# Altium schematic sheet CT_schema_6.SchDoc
size 226 x 144 mm
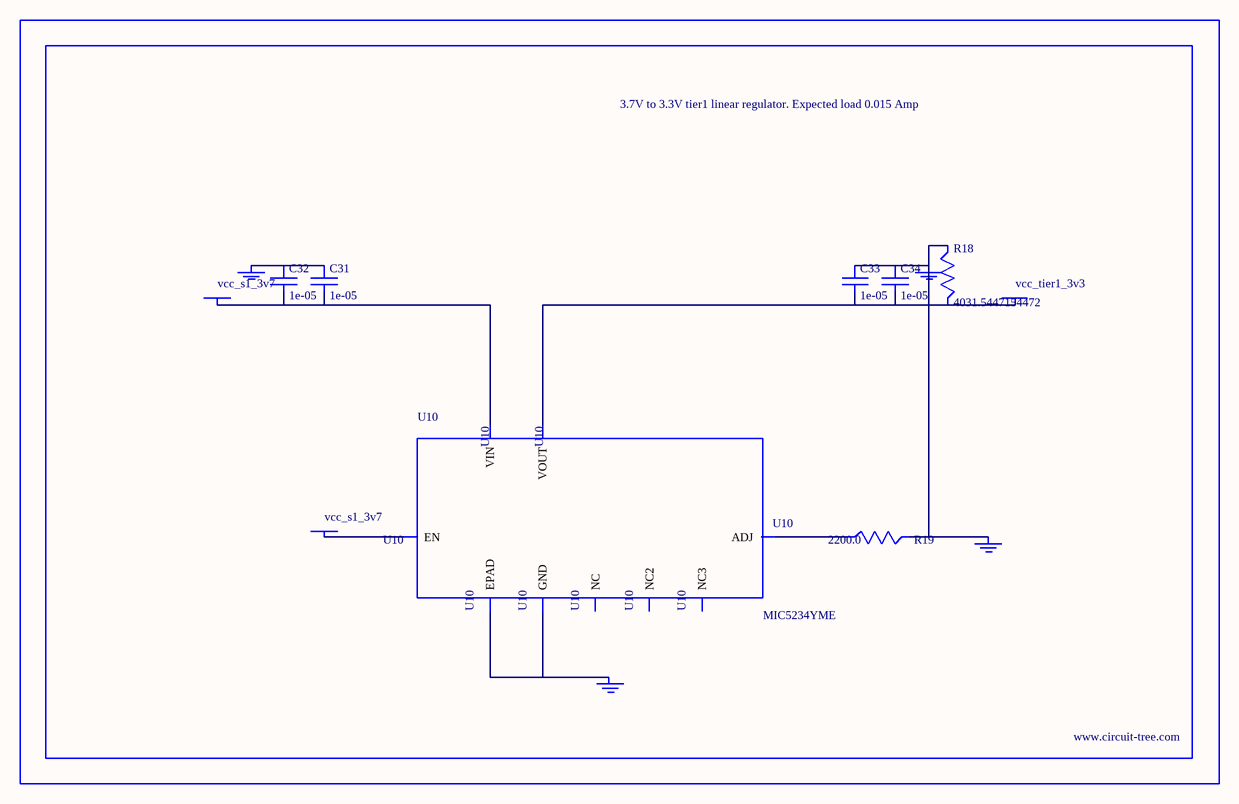
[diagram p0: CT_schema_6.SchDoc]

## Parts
BORDER5  (no value)
C31  1e-05  [C1210]
C32  1e-05  [C1210]
C33  1e-05  [C1210]
C34  1e-05  [C1210]
GND_INSTANCE_5_0  (no value)
GND_INSTANCE_5_1  (no value)
GND_INSTANCE_5_2  (no value)
GND_INSTANCE_5_3  (no value)
POWER_INSTANCE_5_0  vcc_tier1_3v3
POWER_INSTANCE_5_1  vcc_s1_3v7
POWER_INSTANCE_5_2  vcc_s1_3v7
R18  4031.5447154472  [R0603]
R19  2200.0  [R0603]
U10  MIC5234YME  [SOIC-8_EP]

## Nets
NetC31_1: C31.1 C32.1 GND_INSTANCE_5_3.0(GND)
NetC31_2: C31.2 C32.2 POWER_INSTANCE_5_2.0(PWR) U10.8(VIN)
NetC33_1: C33.1 C34.1 GND_INSTANCE_5_0.0(GND) GND_INSTANCE_5_1.0(GND) R18.1 R19.2
NetC33_2: C33.2 C34.2 POWER_INSTANCE_5_0.0(PWR) R18.2 U10.1(VOUT)
NetGND_INSTANCE_5_2_0: GND_INSTANCE_5_2.0(GND) U10.7(GND) U10.EPAD
NetPOWER_INSTANCE_5_1_0: POWER_INSTANCE_5_1.0(PWR) U10.5(EN)
NetR19_1: R19.1 U10.4(ADJ)

Not connected (* = marked no-connect by the designer): U10 2(NC) 3(NC2) 6(NC3)

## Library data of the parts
BORDER5 = BORDER_PAGE5
C31-C34 = C1210C106K5PACTU
GND_INSTANCE_5_0-GND_INSTANCE_5_3 = GND
POWER_INSTANCE_5_0-POWER_INSTANCE_5_2 = PWR
R18 = R18
R19 = RC0603JR-072K2L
